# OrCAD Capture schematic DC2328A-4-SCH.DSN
size Custom; title: LOW EMI INVERTING BUCK-BOOST; rev: 4; company: TM; note: MODULE REGULATOR
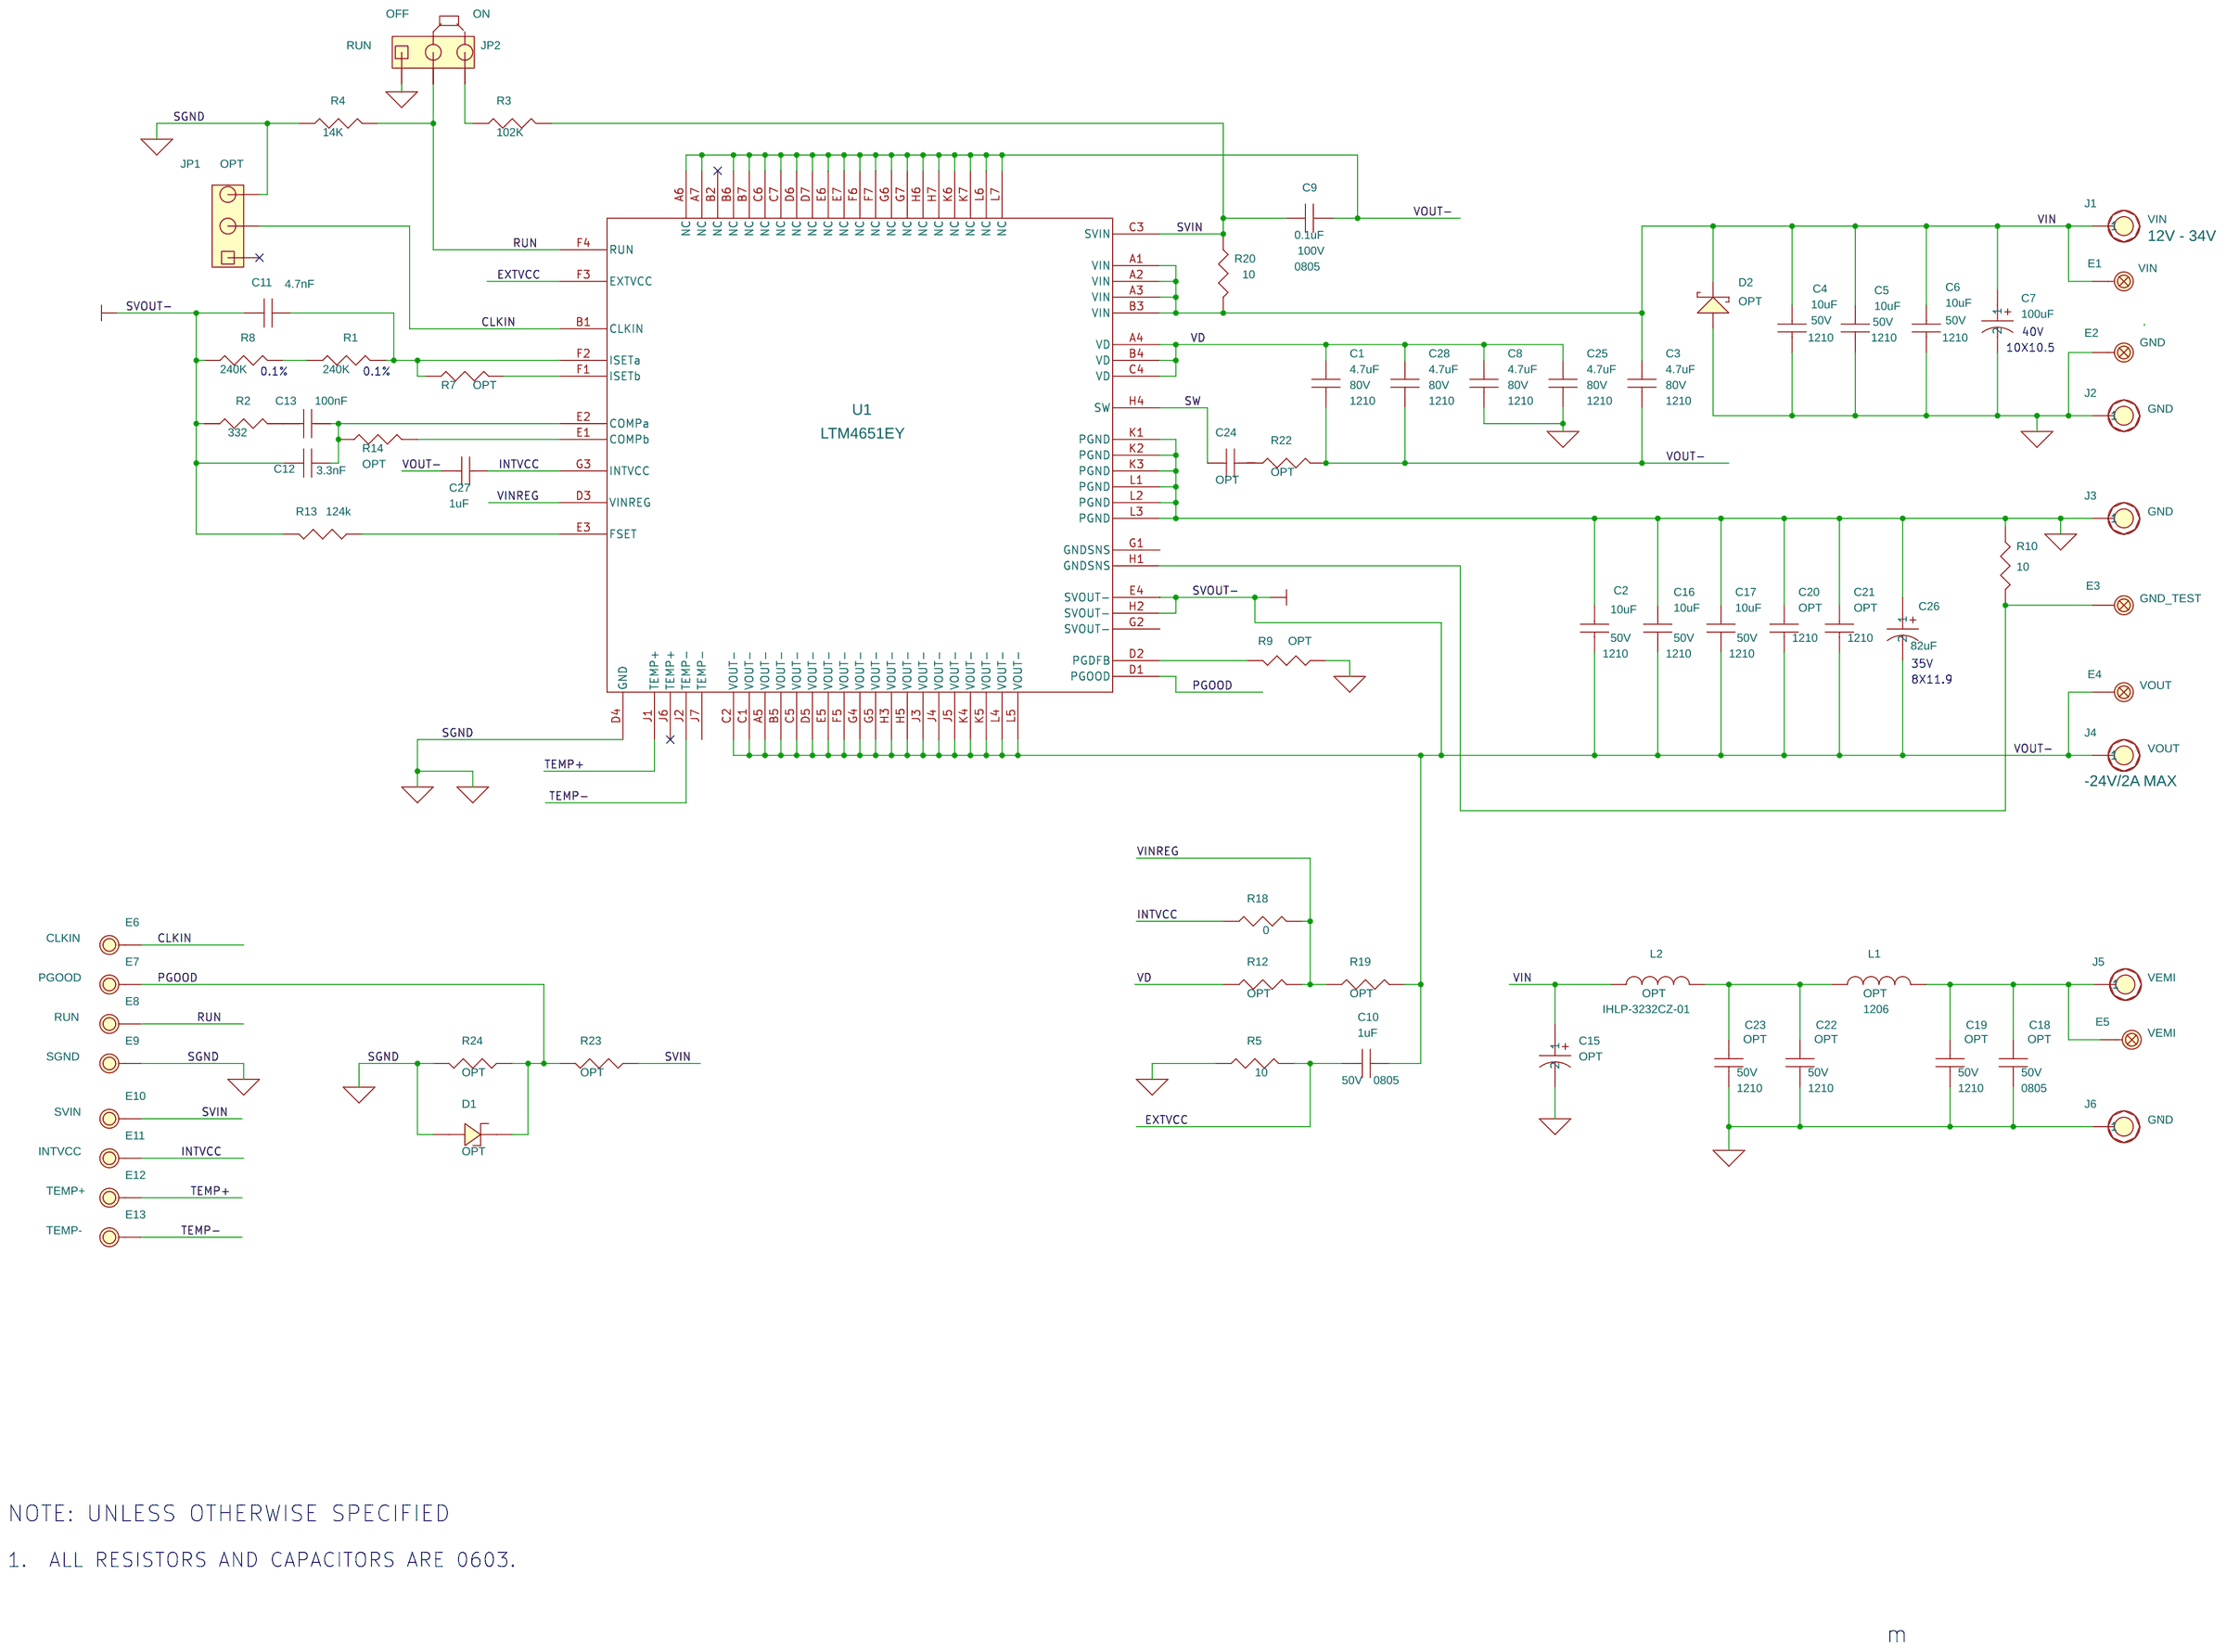
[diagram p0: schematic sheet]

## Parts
C1  4.7uF  [1210]
C2  10uF  [1210]
C3  4.7uF  [1210]
C4  10uF  [1210]
C5  10uF  [1210]
C6  10uF  [1210]
C7  100uF  [C-10X10.5]
C8  4.7uF  [1210]
C9  0.1uF  [0805]
C10  1uF  [0805]
C11  4.7nF  [0603]
C12  3.3nF  [0603]
C13  100nF  [0603]
C15  OPT  [C-10X10.2]
C16  10uF  [1210]
C17  10uF  [1210]
C18  OPT  [0805]
C19  OPT  [1210]
C20  OPT  [1210]
C21  OPT  [1210]
C22  OPT  [1210]
C23  OPT  [1210]
C24  OPT  [0603]
C25  4.7uF  [1210]
C26  82uF  [C-8X10.5]
C27  1uF  [0603]
C28  4.7uF  [1210]
D1  OPT  [SOT23]
D2  OPT  [SMA-SMB]
E1  Testpoint  [MM/2308]
E2  Testpoint  [MM/2308]
E3  Testpoint  [MM/2308]
E4  Testpoint  [MM/2308]
E5  Testpoint  [MM/2308]
E6  Turret  [MM/2501]
E7  Turret  [MM/2501]
E8  Turret  [MM/2501]
E9  Turret  [MM/2501]
E10  Turret  [MM/2501]
E11  Turret  [MM/2501]
E12  Turret  [MM/2501]
E13  Turret  [MM/2501]
J1  Banana Jack  [KEY-575-4]
J2  Banana Jack  [KEY-575-4]
J3  Banana Jack  [KEY-575-4]
J4  Banana Jack  [KEY-575-4]
J5  Banana Jack  [KEY-575-4]
J6  Banana Jack  [KEY-575-4]
JP1  3 Pins 2mm Ctrs.  [commcon2802s03g2]
JP2  3 Pins 2mm Ctrs.  [commcon2802s03g2]
L1  OPT  [1206]
L2  OPT  [IHLP-3232CZ-01]
R1  240K  [0603]
R2  332  [0603]
R3  102K  [0603]
R4  14K  [0603]
R5  10  [0603]
R7  OPT  [0603]
R8  240K  [0603]
R9  OPT  [0603]
R10  10  [0603]
R12  OPT  [0603]
R13  124k  [0603]
R14  OPT  [0603]
R18  0  [0603]
R19  OPT  [0603]
R20  10  [0603]
R22  OPT  [0603]
R23  OPT  [0603]
R24  OPT  [0603]
U1  LTM4651EY  [BGA77-15X9X5.01]
XJP2  2mm Ctrs.

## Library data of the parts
C1 C3 C8 C25 C28 = CAP_1uF_10%_6.3V_0402_SS: VOL: 80V
C2 C16 C17 C20 C21 = CAP_1uF_10%_6.3V_0402_SS: TOL: 20%; VOL: 50V
C4-C6 C18 C19 C22 C23 = CAP_1uF_10%_6.3V_0402_SS: VOL: 50V
C7 = TPSE686M020: 1ST PART FIELD: 35V; 2ND PART FIELD: 20%, 7343H; 3RD PART FIELD: SP; 4TH PART FIELD: PANASONIC; 5TH PART FIELD: EEFUE0J151R; 7TH PART FIELD: CAP.
C9 C24 = CAP_0.01uF_10%_10V_0201: VOL: 100V
C10 C11 = CAP_0.01uF_10%_10V_0201: VOL: 50V
C12 C13 = CAP_0.01uF_10%_10V_0201: LTC PKG: 0805; VOL: 50V
C15 = TPSE686M020_1: 1ST PART FIELD: 35V; 2ND PART FIELD: 20%, 7343H; 3RD PART FIELD: SP; 4TH PART FIELD: PANASONIC; 5TH PART FIELD: EEFUE0J151R; 7TH PART FIELD: CAP.
C26 = TPSE686M020_2: 1ST PART FIELD: 35V; 2ND PART FIELD: 20%, 7343H; 3RD PART FIELD: SP; 4TH PART FIELD: PANASONIC; 5TH PART FIELD: EEFUE0J151R; 7TH PART FIELD: CAP.
C27 = CAP_0.01uF_10%_10V_0201: LTC PKG: 0805; VOL: 25V
D1 = BZX84C2V4-C51
D2 = DIODE-1N4148WS-V-SOD323
E1 = mill-max-2308-2: 9th Part Field: VIN
E2 = mill-max-2308-2: 9th Part Field: GND
E3 = mill-max-2308-2: 9th Part Field: GND_TEST
E4 = mill-max-2308-2: 9th Part Field: VOUT
E5 = mill-max-2308-2: 9th Part Field: VEMI
E6 = MillMax-2501-2_0: 9th Part Field: CLKIN
E7 = MillMax-2501-2_0: 9th Part Field: PGOOD
E8 = MillMax-2501-2_0: 9th Part Field: RUN
E9 = MillMax-2501-2_0: 9th Part Field: SGND
E10 = MillMax-2501-2_0: 9th Part Field: SVIN
E11 = MillMax-2501-2_0: 9th Part Field: INTVCC
E12 = MillMax-2501-2_0: 9th Part Field: TEMP+
E13 = MillMax-2501-2_0: 9th Part Field: TEMP-
J1 = Keystone-575-4_0: 10th Part Field: 12V - 34V; 9th Part Field: VIN
J2 J6 = Keystone-575-4_0: 9th Part Field: GND
J3 = Keystone-575-4_0: 10th Part Field: -24V/2A MAX; 9th Part Field: GND
J4 = Keystone-575-4_0: 9th Part Field: VOUT
J5 = Keystone-575-4_0: 10th Part Field: 28V - 58V; 9th Part Field: VEMI
JP1 = Commcon2802s03g2: 11th Part Field: BURST; 12th Part Field: OPT; 9th Part Field: FORCED CCM
JP2 = Commcon2802s03g2: 11th Part Field: ON; 12th Part Field: RUN; 9th Part Field: OFF
L1 L2 = FDA1254-4R7M
R1 = RES_0_Ohm_0%_0201_4: LTC PKG: 2512
R2 = RES_0_Ohm_0%_0201_3: LTC PKG: 2512
R3 = RES_0_Ohm_0%_0201_12: LTC PKG: 2512
R4 = RES_0_Ohm_0%_0201: LTC PKG: 2512
R5 = RES_0_Ohm_0%_0201_11: LTC PKG: 2512
R7 = RES_0_Ohm_0%_0201_15: LTC PKG: 2512
R8 = RES_0_Ohm_0%_0201_1: LTC PKG: 2512
R9 = RES_0_Ohm_0%_0201_2: LTC PKG: 2512
R10 = CR16-100JM
R12 = RES_0_Ohm_0%_0201_7: LTC PKG: 2512
R13 = RES_0_Ohm_0%_0201_16: LTC PKG: 2512
R14 = RES_0_Ohm_0%_0201_6: LTC PKG: 2512
R18 = RES_0_Ohm_0%_0201_10: LTC PKG: 2512
R19 = RES_0_Ohm_0%_0201_5: LTC PKG: 2512
R20 = RES_0_Ohm_0%_0201_13: LTC PKG: 2512
R22 = RES_0_Ohm_0%_0201_9: LTC PKG: 2512
R23 = RES_0_Ohm_0%_0201_14: LTC PKG: 2512
R24 = RES_0_Ohm_0%_0201_8: LTC PKG: 2512
U1 = LTM4651EY_0
XJP2 = CommconCCIJ2MM-138G

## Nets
GND_POWER: C2.1 C4.2 C5.2 C6.2 C7.2 C8.2 C15.2 C16.1 C17.1 C18.2 C19.2 C20.1 C21.1 C22.2 C23.2 C25.2 C26.1 D1.1(ANODE) D2.2 E2.1 E9.1 J2.1 J3.1 J6.1 JP1.3 JP2.1 R4.1 R5.1 R9.1 R10.1 R24.2 U1.D4(GND) U1.K1(PGND) U1.K2(PGND) U1.K3(PGND) U1.L1(PGND) U1.L2(PGND) U1.L3(PGND)
SVIN: C9.1 E10.1 R3.2 R20.1 R23.1 U1.C3(SVIN)
VIN: C3.1 C4.1 C5.1 C6.1 C7.1 C15.1 D2.1 E1.1 J1.1 L2.2 R20.2 U1.A1(VIN) U1.A2(VIN) U1.A3(VIN) U1.B3(VIN)
VINREG: R12.2 R18.2 R19.1 U1.D3(VINREG)
CLKIN: E6.1 JP1.2 U1.B1(CLKIN)
EXTVCC: C10.2 R5.2 U1.F3(EXTVCC)
INTVCC: C27.1 E11.1 R18.1 U1.G3(INTVCC)
PGOOD: D1.3(CATHODE) E7.1 R23.2 R24.1 U1.D1(PGOOD)
RUN: E8.1 JP2.2 R4.2 U1.F4(RUN)
SW: C24.1 U1.H4(SW)
TEMP+: E12.1 U1.J1(TEMP+)
TEMP-: E13.1 U1.J2(TEMP-) U1.J7(TEMP-)
VD: C1.1 C8.1 C25.1 C28.1 R12.1 U1.A4(VD) U1.B4(VD) U1.C4(VD)
VOUT-: C1.2 C2.2 C3.2 C9.2 C10.1 C11.2 C12.2 C16.2 C17.2 C20.2 C21.2 C26.2 C27.2 C28.2 E4.1 J4.1 R2.1 R8.1 R13.2 R19.2 R22.2 U1.A5(VOUT-) U1.A6(NC) U1.A7(NC) U1.B5(VOUT-) U1.B6(NC) U1.B7(NC) U1.C1(VOUT-) U1.C2(VOUT-) U1.C5(VOUT-) U1.C6(NC) U1.C7(NC) U1.D5(VOUT-) U1.D6(NC) U1.D7(NC) U1.E4(SVOUT-) U1.E5(VOUT-) U1.E6(NC) U1.E7(NC) U1.F5(VOUT-) U1.F6(NC) U1.F7(NC) U1.G4(VOUT-) U1.G5(VOUT-) U1.G6(NC) U1.G7(NC) U1.H2(SVOUT-) U1.H3(VOUT-) U1.H5(VOUT-) U1.H6(NC) U1.H7(NC) U1.J3(VOUT-) U1.J4(VOUT-) U1.J5(VOUT-) U1.K4(VOUT-) U1.K5(VOUT-) U1.K6(NC) U1.K7(NC) U1.L4(VOUT-) U1.L5(VOUT-) U1.L6(NC) U1.L7(NC)
N153198: R13.1 U1.E3(FSET)
N261200: R9.2 U1.D2(PGDFB)
N296916: C12.1 C13.1 R14.1 U1.E2(COMPa)
N16756115: C11.1 R1.2 R7.1 U1.F2(ISETa)
N16767662: R14.2 U1.E1(COMPb)
N16782870: R7.2 U1.F1(ISETb)
N16926115: C18.1 C19.1 E5.1 J5.1 L1.1
N16947176: C22.1 C23.1 L1.2 L2.1
N17060868: E3.1 R10.2 U1.H1(GNDSNS)
N17284876: R1.1 R8.2
N17499368: JP2.3 R3.1
N17513246: C24.2 R22.1
N17522378: C13.2 R2.2

Not connected (* = marked no-connect by the designer): JP1 1*; U1 B2(NC)* G1(GNDSNS) G2(SVOUT-) J6(TEMP+)*

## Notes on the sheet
- 40V
- 10X10.5
- 0.1%
- 0.1%
- 35V
- 8X11.9
- NOTE: UNLESS OTHERWISE SPECIFIED
- 1.  ALL RESISTORS AND CAPACITORS ARE 0603.
- m
